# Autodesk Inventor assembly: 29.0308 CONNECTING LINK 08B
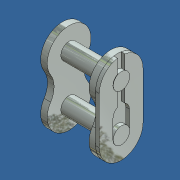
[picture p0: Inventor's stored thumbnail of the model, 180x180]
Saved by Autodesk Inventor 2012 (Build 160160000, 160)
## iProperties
Created: 2013-10
Part Number: 29.0308 CONNECTING LINK 08B
Document SubType Name: Assembly
Designer: Admin
Author: Admin
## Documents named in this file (4)
- C:\Andys Backup Data\ANDY'S INVENTOR\INVENTOR LIBRARIES\PARTS LIBRARY\COUNTER WEIGHT SYSTEM HEAVY\29.0308 CONNECTING LINK 08B.iam
- C:\Andys Backup Data\ANDY'S INVENTOR\INVENTOR LIBRARIES\PARTS LIBRARY\COUNTER WEIGHT SYSTEM HEAVY\SUBCOMPONENTS\29.0308 CONNECTING LINK MALE.ipt
- C:\Andys Backup Data\ANDY'S INVENTOR\INVENTOR LIBRARIES\PARTS LIBRARY\COUNTER WEIGHT SYSTEM HEAVY\SUBCOMPONENTS\29.0308 CONNECTING LINK FEMALE.ipt
- C:\Andys Backup Data\ANDY'S INVENTOR\INVENTOR LIBRARIES\PARTS LIBRARY\COUNTER WEIGHT SYSTEM HEAVY\SUBCOMPONENTS\29.0308 CONNECTING LINK CLIP.ipt
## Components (3 placed, 3 different names)
1. 29.0308 CONNECTING LINK MALE:1 — Mate:1, Mate:2, Mate:3, Mate:4, Mate:6, Mate:7, Flush:1, Mate:8
2. 29.0308 CONNECTING LINK FEMALE:1 — Mate:1, Mate:2, Mate:5, Mate:6
3. 29.0308 CONNECTING LINK CLIP:1 — Mate:3, Mate:4, Mate:5, Angle:1
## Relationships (10: Mate 8, Flush 1, Angle 1)
- Mate:1: 29.0308 CONNECTING LINK MALE:1 ↔ 29.0308 CONNECTING LINK FEMALE:1
- Mate:2: 29.0308 CONNECTING LINK MALE:1 ↔ 29.0308 CONNECTING LINK FEMALE:1
- Mate:3: 29.0308 CONNECTING LINK MALE:1 ↔ 29.0308 CONNECTING LINK CLIP:1
- Mate:4: 29.0308 CONNECTING LINK MALE:1 ↔ 29.0308 CONNECTING LINK CLIP:1
- Mate:5: 29.0308 CONNECTING LINK FEMALE:1 ↔ 29.0308 CONNECTING LINK CLIP:1
- Mate:6: 29.0308 CONNECTING LINK MALE:1 ↔ 29.0308 CONNECTING LINK FEMALE:1
- Mate:7: 29.0308 CONNECTING LINK MALE:1
- Flush:1: 29.0308 CONNECTING LINK MALE:1
- Angle:1: 29.0308 CONNECTING LINK CLIP:1
- Mate:8: 29.0308 CONNECTING LINK MALE:1
